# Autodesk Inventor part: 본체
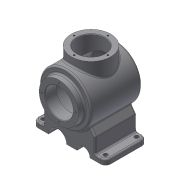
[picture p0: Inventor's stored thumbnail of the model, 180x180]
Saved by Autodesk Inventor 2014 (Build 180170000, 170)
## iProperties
Created: 2018-08
Part Number: 본체
Material: 일반
Document SubType Name: Modeling
Designer: 601-24
Density: 1 g/cm^3
Appearance: 기본값
Author: 601-24
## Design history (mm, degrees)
sketch "스케치1"
  geometry: L1 (-54, 50)-(42.671, 50); L2 (54, 50)-(54, 0); L3 (54, 0)-(-54, 0); L4 (-54, 0)-(-54, 50); L5 (-54, -50)-(42.671, -50); L6 (54, -50)-(54, 0); L7 (-54, 0)-(-54, -50); L8 (42.671, 50)-(54, 50); L9 (42.671, -50)-(54, -50); A1 r 116 centre (-62, 0) between (42.671, -50) and (42.671, 50); 2 further points
  constraints: 18 end point, 3 parallel, 3 point on circle, 2 horizontal, 2 perpendicular, 2 symmetric about line, 1 centre point, 1 coincident, 1 midpoint, 1 tangent
  dimensions: "d0" = 100 diameter of L1 L3; "d1" = 108 distance of L1.start L2.start; "d2" = 232 diameter of A1
revolve "회전1" sketch "스케치1" stored, may be unused: angle "d3" = 90 deg
sketch "스케치14"
  geometry: L1 (-54, 50)-(54, 50); L2 (54, 50)-(54, 0); L3 (54, 0)-(-54, 0); L4 (-54, 0)-(-54, 50); L5 (-54, 50)-(42.671, 50) reference; 2 further points
  constraints: 8 end point, 2 parallel, 1 coincident, 1 collinear, 1 horizontal, 1 midpoint, 1 perpendicular
  dimensions: "d85" = 108 distance of L1.start L1.end
revolve "회전7" sketch "스케치14" stored, may be unused: angle "d86" = 90 deg
sketch "스케치5"
  geometry: L1 (-42, 64.768)-(-4, 64.768); L2 (-4, 64.768)-(-4, -0.232); L3 (-4, -0.232)-(-42, -0.232); L4 (-42, -0.232)-(-42, 64.768); L5 (-54, -50)-(-54, 50) reference
  constraints: 8 end point, 2 parallel, 1 horizontal, 1 perpendicular
  dimensions: "d57" = 50 distance between parallel lines of L2 L5; "d58" = 65 distance of L3.end L1.start; "d59" = 76 diameter of L4 L2
revolve "회전5" sketch "스케치5" stored, may be unused: angle "d27" = 90 deg
sketch "스케치3"
  geometry: L1 (-54, -50)-(-54, 50) reference; L2 (-66, 38)-(-54, 38); L3 (-54, 38)-(-54, 0); L4 (-54, 0)-(-66, 0); L5 (-66, 0)-(-66, 38); 1 further point
  constraints: 8 end point, 2 parallel, 1 horizontal, 1 midpoint, 1 perpendicular
  dimensions: "d10" = 76 diameter of L2 L4; "d11" = 12 distance of L2.start L2.end
revolve "회전3" sketch "스케치3" stored, may be unused: angle "d12" = 90 deg
sketch "스케치2"
  geometry: L1 (-54, 50)-(42.671, 50) reference; L2 (-54, -50)-(-54, 50) reference; L3 (-54, -50)-(42.671, -50) reference; L4 (36.163, 40)-(-44, 40); L5 (-44, 40)-(-44, 0); L6 (-54, 0)-(44, 0); L7 (-54, -38)-(-54, 38) reference; L8 (-66, -38)-(-66, 38) reference; L9 (-66, 27)-(-44, 27); L10 (-44, 27)-(-44, 0); L11 (-44, 0)-(-66, 0); L12 (-66, 0)-(-66, 27); A1 r 116 centre (-62, 0) between (42.671, -50) and (42.671, 50) reference; A2 r 106 centre (-62, 0) between (44, 0) and (36.163, 40); 2 further points
  constraints: 14 end point, 3 point on line, 2 parallel, 2 point on circle, 1 centre point, 1 collinear, 1 horizontal, 1 midpoint, 1 perpendicular
  dimensions: "d4" = 10 distance between parallel lines of L1 L4; "d6" = 10 radial gap between concentric circles of A1 A2; "d13" = 22 distance of L9.start L9.end; "d14" = 54 diameter of L9 L11; "d70" = 80 diameter of L4 L6 (derived)
revolve "회전4" sketch "스케치2" stored, may be unused: angle "d15" = 90 deg
sketch "스케치6"
  geometry: L1 (-42, 64.768)-(34, 64.768) reference; L2 (-31, 64.768)-(-4, 64.768); L3 (-4, 64.768)-(-4, 0); L4 (-4, 0)-(-31, 0); L5 (-31, 0)-(-31, 64.768); L6 (-54, -50)-(-54, 50) reference; 1 further point
  constraints: 8 end point, 2 parallel, 1 horizontal, 1 perpendicular, 1 point on line
  dimensions: "d60" = 50 distance between parallel lines of L3 L6; "d61" = 54 diameter of L5 L3
revolve "회전6" sketch "스케치6" stored, may be unused: angle "d29" = 90 deg
sketch "스케치4"
  geometry: C1 r 38 at (0, 0) reference; A1 r 32.5 centre (0, 0) between (0, 32.5) and (-32.5, 0); 2 further points
  constraints: 4 point on circle, 1 centre point, 1 coincident
  dimensions: "d16" = 65 diameter of A1
hole "구멍1" sketch "스케치4" at (0, 32.5), (-32.5, 0), (32.5, 0), (0, -32.5) diameter "d17" = 3.242; stored, may be unused: countersink angle "d21" = 90 deg, drill point angle "d23" = 118 deg; dims "d18" = 8, "d19" = 4, "d20" = 2, "d22" = 10
node "작업 평면1"
sketch "스케치9"
  geometry: L1 (70, -72)-(70, -82.232); L2 (-70, -82.232)-(-70, -72.232); L3 (0, 0)-(0, -82); L4 (-50, -72.232)-(-50, -43.437); L5 (50, -72)-(50, -43.437); L6 (-50, -43.437)-(-40.304, -29.59); L7 (40.304, -29.59)-(50, -43.437); L8 (-70, -72.232)-(-50, -72.232); L9 (50, -72)-(70, -72); L10 (70, -82.232)-(39.998, -82.232); L11 (15, -82)-(-5, -82); L12 (-39.998, -82.232)-(-70, -82.232); L13 (-38, 64.768)-(38, 64.768) reference; A1 r 50 centre (0, 0) between (-40.304, -29.59) and (40.304, -29.59) reference; A2 r 12.5 centre (27.5, -82) between (39.998, -82.232) and (15, -82); A3 r 17.5 centre (-22.5, -82) between (-5, -82) and (-39.998, -82.232)
  constraints: 24 end point, 10 parallel, 6 point on circle, 2 centre point, 2 horizontal, 2 perpendicular, 1 point on line
  dimensions: "d39" = 10 distance of L2.start L2.end; "d40" = 82 distance of L3.end L3.start; "d41" = 20 distance between parallel lines of L2 L4; "d42" = 20 distance between parallel lines of L1 L5; "d43" = 140 distance of L1.end L2.start; "d46" = 35 deg angle of L1 L7; "d47" = 35 deg angle of L6 L2; "d48" = 25 diameter of A2; "d49" = 35 diameter of A3; "d50" = 27.5 distance from line of L3 A2.centre; "d51" = 22.5 distance from line of A3.centre L3; "d91" = 147 distance between parallel lines of L13 L12
extrude "돌출1" join sketch "스케치9" distance "d52" = 80; taper "d53" = 0 deg
sketch "스케치11"
  geometry: C1 r 38 at (0, 0); A1 r 32.5 centre (0, 0) between (0, 32.5) and (-32.5, 0); 2 further points
  constraints: 4 point on circle, 2 centre point, 1 coincident
  dimensions: "d63" = 65 diameter of A1
hole "구멍3" sketch "스케치11" at (0, 32.5), (-32.5, 0), (32.5, 0), (0, -32.5) diameter "d69" = 3.242; stored, may be unused: drill point angle "d64" = 118 deg, countersink angle "d65" = 90 deg; dims "d62" = 8, "d66" = 2, "d67" = 4, "d68" = 10
fillet "모깎기1" dims "d71" = 10
sketch "스케치12"
  geometry: A1 r 10 centre (10, 70) between (20, 70) and (10, 80) reference; A2 r 10 centre (10, 10) between (10, 0) and (20, 10) reference; A3 r 10 centre (-110, 70) between (-110, 80) and (-120, 70) reference; A4 r 10 centre (-110, 10) between (-120, 10) and (-110, 0) reference; 5 further points
  constraints: 4 coincident
hole "구멍4" sketch "스케치12" at (10, 70), (10, 10), (-110, 70), (-110, 10) diameter "d72" = 8; stored, may be unused: countersink angle "d76" = 90 deg, drill point angle "d78" = 118 deg; dims "d73" = 8, "d74" = 4, "d75" = 2, "d77" = 10
fillet "모깎기2" dims "d79" = 3
fillet "모깎기3" dims "d80" = 3
chamfer "모따기1" distance "d81" = 1; stored, may be unused: second distance "d82" = 2, angle "d83" = 45 deg
node "작업 평면2"
sketch "스케치15"
  geometry: L1 (54, -50)-(54, 50) reference; L2 (-51, 50)-(54, 50) reference; L3 (-51, -50)-(54, -50) reference; L4 (-177.739, 0)-(54, 0); A1 r 116 centre (-62, 0) between (42.671, -50) and (42.671, 50); 1 further point
  constraints: 3 point on circle, 3 point on line, 2 end point, 1 centre point, 1 midpoint, 1 parallel
  dimensions: "d88" = 232 diameter of A1
revolve "회전8" sketch "스케치15" stored, may be unused: angle "d89" = 90 deg
fillet "모깎기4" dims "d90" = 3
node "솔리드1"
node "투영된 루프1"
other parameters: "d38" = -8
